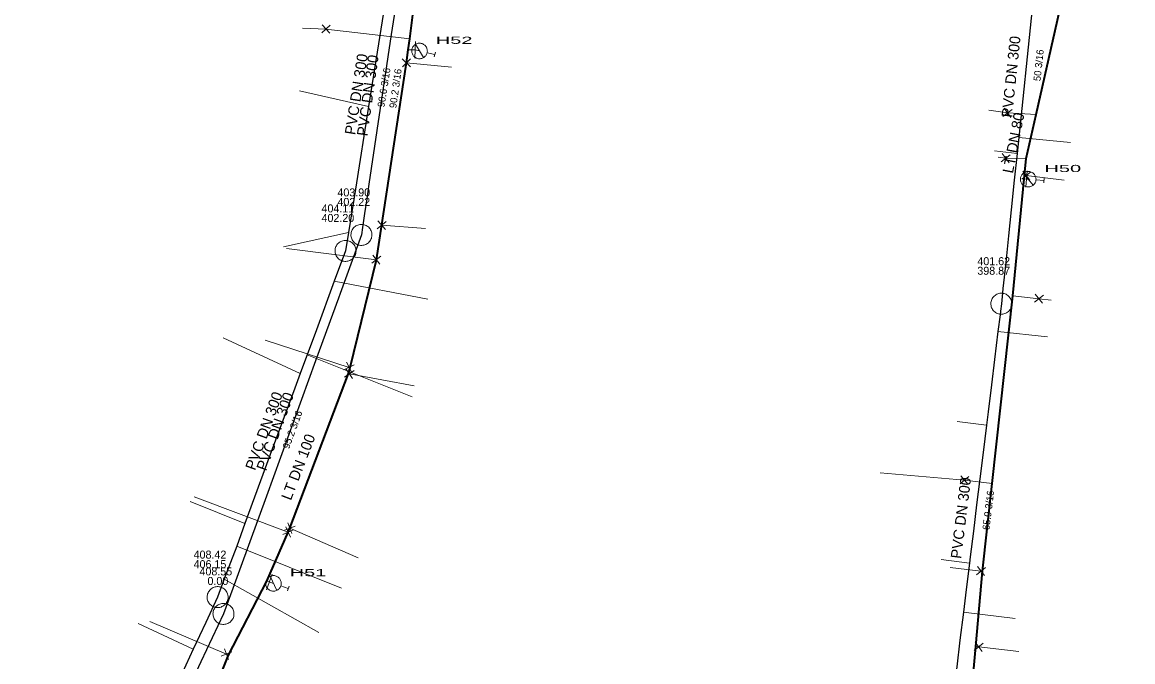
# Model space of a CAD drawing. Extents: x -772952 to -772403, y -1033777 to -1033210.
# Drawn here: x -772856.8 to -772731.9, y -1033502.9 to -1033431 of the extents above; entities that cross this region are included whole.
import ezdxf

# ---------------------------------------------------------------- set-up
doc = ezdxf.new("R2010")
doc.units = 0
doc.header["$LTSCALE"] = 0.36
for name, color, linetype, lineweight in [('15', 7, 'Continuous', 13), ('16', 7, 'Continuous', 35), ('2', 7, 'Continuous', 25), ('20', 7, 'Continuous', 13), ('4', 7, 'Continuous', 13), ('57', 7, 'Continuous', 13), ('59', 7, 'Continuous', 13)]:
    doc.layers.add(name, color=color, linetype=linetype, lineweight=lineweight)
for name, color, linetype in [('17', 7, 'Continuous'), ('3', 7, 'Continuous'), ('6', 7, 'Continuous')]:
    doc.layers.add(name, color=color, linetype=linetype)

msp = doc.modelspace()

# ---------------------------------------------------------------- linework, layer by layer
at = {"layer": '15'}
for p, q in [((-772822.125, -1033431.276), (-772823.076, -1033432.164)), ((-772822.161, -1033432.191), (-772823.039, -1033431.245)), ((-772812.608, -1033435), (-772812.532, -1033433.14)), ((-772813.093, -1033435.978), (-772814.014, -1033435.057)), ((-772814.009, -1033435.973), (-772813.093, -1033435.063)), ((-772745.439, -1033440.76), (-772746.482, -1033441.54)), ((-772745.574, -1033441.665), (-772746.345, -1033440.63)), ((-772745.654, -1033445.857), (-772746.694, -1033446.64)), ((-772745.786, -1033446.762), (-772746.56, -1033445.73)), ((-772744.369, -1033448.596), (-772743.344, -1033447.793)), ((-772744.254, -1033447.688), (-772743.46, -1033448.706)), ((-772743.919, -1033449.512), (-772743.748, -1033447.658)), ((-772816.822, -1033454.194), (-772815.835, -1033453.345)), ((-772816.749, -1033453.282), (-772815.909, -1033454.262)), ((-772816.409, -1033457.255), (-772817.436, -1033458.055)), ((-772816.527, -1033458.163), (-772817.317, -1033457.143)), ((-772742.841, -1033461.537), (-772742.038, -1033462.547)), ((-772742.947, -1033462.446), (-772741.93, -1033461.634)), ((-772819.416, -1033469.467), (-772820.575, -1033470.059)), ((-772820.496, -1033470.866), (-772819.424, -1033470.128)), ((-772820.326, -1033469.967), (-772819.597, -1033471.031)), ((-772819.702, -1033470.336), (-772820.287, -1033469.186)), ((-772750.302, -1033482.042), (-772751.299, -1033482.879)), ((-772750.386, -1033482.953), (-772751.214, -1033481.963)), ((-772827.265, -1033488.084), (-772826.054, -1033487.606)), ((-772826.591, -1033488.876), (-772827.121, -1033487.7)), ((-772826.897, -1033487.246), (-772826.425, -1033488.448)), ((-772826.265, -1033488.021), (-772827.451, -1033488.559)), ((-772748.437, -1033492.271), (-772749.458, -1033493.078)), ((-772748.548, -1033493.179), (-772749.346, -1033492.165)), ((-772829.278, -1033494.765), (-772828.655, -1033493.011)), ((-772833.537, -1033502.607), (-772834.016, -1033501.409)), ((-772749.709, -1033501.591), (-772748.686, -1033500.787)), ((-772749.596, -1033500.683), (-772748.801, -1033501.699)), ((-772833.174, -1033501.767), (-772834.382, -1033502.253))]:
    msp.add_line(p, q, dxfattribs=at)
at = {"layer": '16'}
for points in [[(-772752.004, -1033530.359), (-772751.19, -1033518.811), (-772750.826, -1033515.51), (-772749.541, -1033501.15), (-772748.782, -1033492.67), (-772747.697, -1033482.83), (-772745.37, -1033461.714), (-772744.103, -1033448.559), (-772744.068, -1033448.195), (-772743.857, -1033446.285), (-772742.735, -1033441.315), (-772739.627, -1033427.552), (-772737.918, -1033409.688), (-772737.464, -1033404.467), (-772736.037, -1033389.46), (-772734.688, -1033370.337), (-772732.3, -1033357.109), (-772731.88, -1033345.97)], [(-772837.765, -1033512.662), (-772833.548, -1033502.146), (-772829.238, -1033493.795), (-772826.857, -1033488.289), (-772826.66, -1033487.846), (-772820.068, -1033470.473), (-772819.886, -1033469.795), (-772816.921, -1033457.655), (-772813.552, -1033435.519), (-772813.35, -1033434.04), (-772813.183, -1033432.822), (-772812.813, -1033430.125), (-772811.638, -1033420.013), (-772811.429, -1033417.653), (-772810.102, -1033408.565), (-772809.872, -1033406.991), (-772809.089, -1033400.644), (-772808.375, -1033395.068), (-772807.557, -1033387.964), (-772806.853, -1033383.381), (-772806.021, -1033377.978)]]:
    msp.add_lwpolyline(points, dxfattribs=at)
at = {"layer": '2'}
for points in [[(-772741.06, -1033409.08), (-772741.253, -1033410.929), (-772741.326, -1033411.63), (-772741.587, -1033414.12), (-772741.871, -1033416.843), (-772742.189, -1033419.878), (-772742.495, -1033422.808), (-772742.806, -1033425.788), (-772743.066, -1033428.271), (-772743.3, -1033430.508), (-772744.701, -1033443.912), (-772744.889, -1033445.705), (-772745.203, -1033448.714), (-772745.553, -1033452.058), (-772745.859, -1033454.983), (-772746.171, -1033457.964), (-772746.344, -1033459.622), (-772746.477, -1033460.894), (-772746.527, -1033461.369), (-772746.66, -1033462.606)], [(-772814.42, -1033419.15), (-772814.998, -1033422.779), (-772815.417, -1033425.405), (-772816.014, -1033429.153), (-772817.813, -1033440.441), (-772819.293, -1033449.728), (-772820.068, -1033454.588), (-772820.4, -1033456.67)], [(-772813.59, -1033421.19), (-772813.756, -1033422.304), (-772813.954, -1033423.632), (-772814.184, -1033425.18), (-772814.339, -1033425.976), (-772814.533, -1033427.52), (-772815.252, -1033432.346), (-772815.998, -1033437.348), (-772816.86, -1033443.13), (-772817.761, -1033449.175), (-772818.006, -1033450.823), (-772818.251, -1033452.464), (-772818.488, -1033454.051), (-772818.61, -1033454.87)], [(-772818.61, -1033454.87), (-772821.012, -1033461.472), (-772821.192, -1033461.989), (-772821.867, -1033463.82), (-772823.76, -1033469.022), (-772829.295, -1033484.231), (-772832.183, -1033492.167), (-772833.081, -1033494.635), (-772834.12, -1033497.49)], [(-772820.4, -1033456.67), (-772821.658, -1033460.076), (-772823.677, -1033465.542), (-772825.485, -1033470.437), (-772826.102, -1033472.107), (-772828.853, -1033479.555), (-772831.719, -1033487.314), (-772832.635, -1033489.888), (-772833.341, -1033491.706), (-772834.069, -1033493.675), (-772834.78, -1033495.6)], [(-772746.66, -1033462.606), (-772746.76, -1033463.455), (-772746.808, -1033463.844), (-772747.038, -1033465.715), (-772747.425, -1033468.865), (-772747.777, -1033471.721), (-772748.153, -1033474.782), (-772748.335, -1033476.264), (-772748.712, -1033479.323), (-772749.08, -1033482.314), (-772749.439, -1033485.239), (-772749.803, -1033488.195), (-772750.155, -1033491.056), (-772750.242, -1033491.766), (-772750.606, -1033494.725), (-772750.924, -1033497.308), (-772751.311, -1033500.451), (-772751.677, -1033503.432), (-772752.043, -1033506.407), (-772752.158, -1033507.342), (-772752.198, -1033507.662), (-772752.29, -1033508.384)], [(-772834.78, -1033495.6), (-772836.114, -1033498.463), (-772837.51, -1033501.461), (-772838.768, -1033504.161), (-772840.12, -1033507.062), (-772842.931, -1033513.095), (-772845.54, -1033518.695), (-772849.358, -1033526.891), (-772852.073, -1033532.717), (-772853.674, -1033536.155), (-772854.426, -1033537.769), (-772855.508, -1033540.092), (-772855.782, -1033540.679), (-772856.3, -1033541.79)], [(-772834.12, -1033497.489), (-772836.663, -1033502.872), (-772837.696, -1033505.057), (-772838.705, -1033507.192), (-772840.489, -1033510.965), (-772843.322, -1033516.96), (-772845.177, -1033520.885), (-772847.84, -1033526.52), (-772850.14, -1033531.386), (-772853.138, -1033537.728), (-772854.606, -1033540.835), (-772856.75, -1033545.37)]]:
    msp.add_lwpolyline(points, dxfattribs=at)
at = {"layer": '20'}
for p, q in [((-772811.613, -1033434.926), (-772812.535, -1033433.438)), ((-772811.211, -1033434.384), (-772810.351, -1033434.587)), ((-772810.289, -1033434.324), (-772810.413, -1033434.851)), ((-772743.075, -1033449.271), (-772744.194, -1033447.925)), ((-772742.752, -1033448.679), (-772741.872, -1033448.76)), ((-772741.847, -1033448.491), (-772741.897, -1033449.03)), ((-772828.124, -1033494.838), (-772828.877, -1033493.258)), ((-772827.665, -1033494.344), (-772826.832, -1033494.64)), ((-772826.742, -1033494.385), (-772826.922, -1033494.895))]:
    msp.add_line(p, q, dxfattribs=at)
for points in [[(-772812.274, -1033435.038), (-772812.186, -1033435.055), (-772812.095, -1033435.062), (-772812.002, -1033435.059), (-772811.913, -1033435.047), (-772811.823, -1033435.025), (-772811.736, -1033434.995), (-772811.654, -1033434.954), (-772811.576, -1033434.907), (-772811.505, -1033434.85), (-772811.438, -1033434.787), (-772811.379, -1033434.717), (-772811.326, -1033434.641), (-772811.282, -1033434.561), (-772811.248, -1033434.476), (-772811.223, -1033434.388), (-772811.206, -1033434.297), (-772811.199, -1033434.207), (-772811.202, -1033434.115), (-772811.216, -1033434.024), (-772811.238, -1033433.934), (-772811.269, -1033433.849), (-772811.307, -1033433.766), (-772811.357, -1033433.689), (-772811.412, -1033433.616), (-772811.476, -1033433.55), (-772811.546, -1033433.49), (-772811.621, -1033433.44), (-772811.703, -1033433.396), (-772811.787, -1033433.361), (-772811.875, -1033433.334), (-772811.964, -1033433.32), (-772812.055, -1033433.313), (-772812.148, -1033433.315), (-772812.237, -1033433.327), (-772812.327, -1033433.349), (-772812.414, -1033433.38), (-772812.496, -1033433.421), (-772812.574, -1033433.468), (-772812.645, -1033433.525), (-772812.712, -1033433.588), (-772812.771, -1033433.658), (-772812.824, -1033433.734), (-772812.866, -1033433.814), (-772812.902, -1033433.898), (-772812.927, -1033433.987), (-772812.944, -1033434.077), (-772812.949, -1033434.169), (-772812.948, -1033434.259), (-772812.934, -1033434.351), (-772812.912, -1033434.44), (-772812.881, -1033434.526), (-772812.843, -1033434.609), (-772812.793, -1033434.686), (-772812.738, -1033434.759), (-772812.674, -1033434.825), (-772812.604, -1033434.885), (-772812.529, -1033434.935), (-772812.447, -1033434.979), (-772812.363, -1033435.013), (-772812.276, -1033435.038)], [(-772743.714, -1033449.474), (-772743.624, -1033449.478), (-772743.533, -1033449.472), (-772743.442, -1033449.457), (-772743.355, -1033449.433), (-772743.27, -1033449.398), (-772743.187, -1033449.356), (-772743.112, -1033449.304), (-772743.041, -1033449.247), (-772742.978, -1033449.18), (-772742.921, -1033449.109), (-772742.872, -1033449.031), (-772742.83, -1033448.949), (-772742.798, -1033448.863), (-772742.776, -1033448.775), (-772742.764, -1033448.684), (-772742.759, -1033448.592), (-772742.765, -1033448.501), (-772742.781, -1033448.411), (-772742.807, -1033448.322), (-772742.841, -1033448.237), (-772742.884, -1033448.157), (-772742.933, -1033448.08), (-772742.993, -1033448.01), (-772743.057, -1033447.946), (-772743.13, -1033447.889), (-772743.208, -1033447.839), (-772743.289, -1033447.8), (-772743.376, -1033447.768), (-772743.464, -1033447.745), (-772743.555, -1033447.731), (-772743.646, -1033447.729), (-772743.737, -1033447.734), (-772743.828, -1033447.75), (-772743.915, -1033447.774), (-772744, -1033447.809), (-772744.083, -1033447.851), (-772744.158, -1033447.902), (-772744.229, -1033447.96), (-772744.292, -1033448.027), (-772744.349, -1033448.098), (-772744.398, -1033448.176), (-772744.44, -1033448.258), (-772744.47, -1033448.344), (-772744.494, -1033448.432), (-772744.506, -1033448.523), (-772744.511, -1033448.615), (-772744.503, -1033448.706), (-772744.489, -1033448.796), (-772744.463, -1033448.885), (-772744.429, -1033448.97), (-772744.386, -1033449.05), (-772744.337, -1033449.127), (-772744.277, -1033449.197), (-772744.213, -1033449.261), (-772744.14, -1033449.318), (-772744.062, -1033449.367), (-772743.981, -1033449.407), (-772743.894, -1033449.439), (-772743.806, -1033449.461), (-772743.716, -1033449.474)], [(-772828.793, -1033494.877), (-772828.707, -1033494.904), (-772828.618, -1033494.921), (-772828.525, -1033494.928), (-772828.435, -1033494.926), (-772828.344, -1033494.914), (-772828.253, -1033494.893), (-772828.168, -1033494.862), (-772828.084, -1033494.823), (-772828.008, -1033494.774), (-772827.935, -1033494.719), (-772827.868, -1033494.656), (-772827.807, -1033494.586), (-772827.755, -1033494.511), (-772827.712, -1033494.431), (-772827.677, -1033494.346), (-772827.65, -1033494.258), (-772827.633, -1033494.168), (-772827.627, -1033494.077), (-772827.63, -1033493.985), (-772827.642, -1033493.894), (-772827.664, -1033493.805), (-772827.692, -1033493.719), (-772827.733, -1033493.636), (-772827.78, -1033493.558), (-772827.837, -1033493.485), (-772827.9, -1033493.418), (-772827.968, -1033493.36), (-772828.045, -1033493.307), (-772828.125, -1033493.264), (-772828.21, -1033493.227), (-772828.297, -1033493.203), (-772828.386, -1033493.186), (-772828.479, -1033493.179), (-772828.569, -1033493.181), (-772828.66, -1033493.193), (-772828.751, -1033493.214), (-772828.836, -1033493.245), (-772828.92, -1033493.283), (-772828.996, -1033493.332), (-772829.069, -1033493.387), (-772829.136, -1033493.451), (-772829.197, -1033493.52), (-772829.247, -1033493.596), (-772829.292, -1033493.675), (-772829.327, -1033493.761), (-772829.354, -1033493.849), (-772829.369, -1033493.939), (-772829.377, -1033494.029), (-772829.374, -1033494.122), (-772829.362, -1033494.213), (-772829.34, -1033494.301), (-772829.311, -1033494.388), (-772829.271, -1033494.47), (-772829.224, -1033494.548), (-772829.167, -1033494.622), (-772829.104, -1033494.689), (-772829.036, -1033494.747), (-772828.959, -1033494.8), (-772828.879, -1033494.843), (-772828.795, -1033494.877)]]:
    msp.add_lwpolyline(points, dxfattribs=at)
at = {"layer": '4'}
for points in [[(-772817.429, -1033454.87), (-772817.435, -1033454.751), (-772817.453, -1033454.634), (-772817.482, -1033454.518), (-772817.523, -1033454.407), (-772817.575, -1033454.3), (-772817.638, -1033454.199), (-772817.711, -1033454.104), (-772817.792, -1033454.018), (-772817.882, -1033453.94), (-772817.98, -1033453.871), (-772818.083, -1033453.813), (-772818.192, -1033453.766), (-772818.306, -1033453.729), (-772818.422, -1033453.704), (-772818.54, -1033453.692), (-772818.659, -1033453.691), (-772818.778, -1033453.702), (-772818.894, -1033453.725), (-772819.008, -1033453.759), (-772819.118, -1033453.805), (-772819.223, -1033453.862), (-772819.321, -1033453.929), (-772819.412, -1033454.005), (-772819.495, -1033454.09), (-772819.569, -1033454.184), (-772819.633, -1033454.284), (-772819.687, -1033454.39), (-772819.73, -1033454.501), (-772819.762, -1033454.615), (-772819.781, -1033454.733), (-772819.789, -1033454.852), (-772819.785, -1033454.97), (-772819.769, -1033455.088), (-772819.741, -1033455.204), (-772819.702, -1033455.316), (-772819.651, -1033455.424), (-772819.59, -1033455.526), (-772819.519, -1033455.622), (-772819.439, -1033455.709), (-772819.35, -1033455.789), (-772819.254, -1033455.859), (-772819.151, -1033455.919), (-772819.043, -1033455.968), (-772818.93, -1033456.006), (-772818.814, -1033456.032), (-772818.696, -1033456.047), (-772818.577, -1033456.05), (-772818.459, -1033456.041), (-772818.341, -1033456.02), (-772818.227, -1033455.987), (-772818.117, -1033455.943), (-772818.011, -1033455.888), (-772817.912, -1033455.822), (-772817.819, -1033455.747), (-772817.735, -1033455.663), (-772817.66, -1033455.571), (-772817.594, -1033455.472), (-772817.538, -1033455.367), (-772817.494, -1033455.257), (-772817.46, -1033455.143), (-772817.439, -1033455.026), (-772817.429, -1033454.907)], [(-772819.218, -1033456.67), (-772819.225, -1033456.551), (-772819.243, -1033456.434), (-772819.272, -1033456.318), (-772819.313, -1033456.207), (-772819.365, -1033456.1), (-772819.428, -1033455.999), (-772819.5, -1033455.904), (-772819.581, -1033455.818), (-772819.672, -1033455.74), (-772819.77, -1033455.671), (-772819.873, -1033455.613), (-772819.982, -1033455.566), (-772820.096, -1033455.529), (-772820.212, -1033455.504), (-772820.33, -1033455.492), (-772820.449, -1033455.491), (-772820.568, -1033455.502), (-772820.684, -1033455.525), (-772820.798, -1033455.559), (-772820.907, -1033455.605), (-772821.012, -1033455.662), (-772821.111, -1033455.729), (-772821.201, -1033455.805), (-772821.285, -1033455.89), (-772821.358, -1033455.984), (-772821.423, -1033456.084), (-772821.477, -1033456.19), (-772821.52, -1033456.301), (-772821.552, -1033456.415), (-772821.571, -1033456.533), (-772821.579, -1033456.652), (-772821.575, -1033456.77), (-772821.559, -1033456.888), (-772821.531, -1033457.004), (-772821.492, -1033457.116), (-772821.441, -1033457.224), (-772821.38, -1033457.326), (-772821.309, -1033457.422), (-772821.228, -1033457.509), (-772821.14, -1033457.589), (-772821.044, -1033457.659), (-772820.941, -1033457.719), (-772820.833, -1033457.768), (-772820.72, -1033457.806), (-772820.603, -1033457.832), (-772820.486, -1033457.847), (-772820.367, -1033457.85), (-772820.249, -1033457.841), (-772820.13, -1033457.82), (-772820.017, -1033457.787), (-772819.907, -1033457.743), (-772819.801, -1033457.688), (-772819.701, -1033457.622), (-772819.608, -1033457.547), (-772819.525, -1033457.463), (-772819.45, -1033457.371), (-772819.384, -1033457.272), (-772819.328, -1033457.167), (-772819.284, -1033457.057), (-772819.25, -1033456.943), (-772819.228, -1033456.826), (-772819.218, -1033456.707)], [(-772745.48, -1033462.606), (-772745.486, -1033462.487), (-772745.504, -1033462.37), (-772745.533, -1033462.254), (-772745.574, -1033462.143), (-772745.626, -1033462.036), (-772745.689, -1033461.935), (-772745.762, -1033461.84), (-772745.843, -1033461.754), (-772745.933, -1033461.676), (-772746.031, -1033461.607), (-772746.134, -1033461.549), (-772746.243, -1033461.502), (-772746.357, -1033461.465), (-772746.473, -1033461.44), (-772746.591, -1033461.428), (-772746.71, -1033461.427), (-772746.829, -1033461.438), (-772746.945, -1033461.461), (-772747.059, -1033461.495), (-772747.169, -1033461.541), (-772747.274, -1033461.598), (-772747.372, -1033461.665), (-772747.463, -1033461.741), (-772747.546, -1033461.826), (-772747.62, -1033461.92), (-772747.684, -1033462.02), (-772747.738, -1033462.126), (-772747.781, -1033462.237), (-772747.813, -1033462.351), (-772747.832, -1033462.469), (-772747.84, -1033462.588), (-772747.836, -1033462.706), (-772747.82, -1033462.824), (-772747.792, -1033462.94), (-772747.753, -1033463.052), (-772747.702, -1033463.16), (-772747.641, -1033463.262), (-772747.57, -1033463.358), (-772747.49, -1033463.445), (-772747.401, -1033463.525), (-772747.305, -1033463.595), (-772747.202, -1033463.655), (-772747.094, -1033463.704), (-772746.981, -1033463.742), (-772746.865, -1033463.768), (-772746.747, -1033463.783), (-772746.628, -1033463.786), (-772746.51, -1033463.777), (-772746.392, -1033463.756), (-772746.278, -1033463.723), (-772746.168, -1033463.679), (-772746.062, -1033463.624), (-772745.963, -1033463.558), (-772745.87, -1033463.483), (-772745.786, -1033463.399), (-772745.711, -1033463.307), (-772745.645, -1033463.208), (-772745.589, -1033463.103), (-772745.545, -1033462.993), (-772745.511, -1033462.879), (-772745.49, -1033462.762), (-772745.48, -1033462.643)], [(-772833.6, -1033495.6), (-772833.606, -1033495.481), (-772833.624, -1033495.364), (-772833.653, -1033495.248), (-772833.694, -1033495.137), (-772833.746, -1033495.03), (-772833.809, -1033494.929), (-772833.882, -1033494.834), (-772833.963, -1033494.748), (-772834.053, -1033494.67), (-772834.151, -1033494.601), (-772834.254, -1033494.543), (-772834.363, -1033494.496), (-772834.477, -1033494.459), (-772834.593, -1033494.434), (-772834.711, -1033494.422), (-772834.83, -1033494.421), (-772834.949, -1033494.432), (-772835.065, -1033494.455), (-772835.179, -1033494.489), (-772835.289, -1033494.535), (-772835.394, -1033494.592), (-772835.492, -1033494.659), (-772835.583, -1033494.735), (-772835.666, -1033494.82), (-772835.74, -1033494.914), (-772835.804, -1033495.014), (-772835.858, -1033495.12), (-772835.901, -1033495.231), (-772835.933, -1033495.345), (-772835.952, -1033495.463), (-772835.96, -1033495.582), (-772835.956, -1033495.7), (-772835.94, -1033495.818), (-772835.912, -1033495.934), (-772835.873, -1033496.046), (-772835.822, -1033496.154), (-772835.761, -1033496.256), (-772835.69, -1033496.352), (-772835.61, -1033496.439), (-772835.521, -1033496.519), (-772835.425, -1033496.589), (-772835.322, -1033496.649), (-772835.214, -1033496.698), (-772835.101, -1033496.736), (-772834.985, -1033496.762), (-772834.867, -1033496.777), (-772834.748, -1033496.78), (-772834.63, -1033496.771), (-772834.512, -1033496.75), (-772834.398, -1033496.717), (-772834.288, -1033496.673), (-772834.182, -1033496.618), (-772834.083, -1033496.552), (-772833.99, -1033496.477), (-772833.906, -1033496.393), (-772833.831, -1033496.301), (-772833.765, -1033496.202), (-772833.709, -1033496.097), (-772833.665, -1033495.987), (-772833.631, -1033495.873), (-772833.61, -1033495.756), (-772833.6, -1033495.637)], [(-772832.94, -1033497.489), (-772832.946, -1033497.37), (-772832.964, -1033497.253), (-772832.993, -1033497.137), (-772833.034, -1033497.026), (-772833.086, -1033496.919), (-772833.149, -1033496.818), (-772833.222, -1033496.723), (-772833.303, -1033496.637), (-772833.393, -1033496.559), (-772833.491, -1033496.49), (-772833.594, -1033496.432), (-772833.703, -1033496.385), (-772833.817, -1033496.348), (-772833.933, -1033496.323), (-772834.051, -1033496.311), (-772834.17, -1033496.31), (-772834.289, -1033496.321), (-772834.405, -1033496.344), (-772834.519, -1033496.378), (-772834.629, -1033496.424), (-772834.733, -1033496.481), (-772834.832, -1033496.548), (-772834.923, -1033496.624), (-772835.006, -1033496.709), (-772835.08, -1033496.803), (-772835.144, -1033496.903), (-772835.198, -1033497.009), (-772835.241, -1033497.12), (-772835.273, -1033497.234), (-772835.292, -1033497.352), (-772835.3, -1033497.471), (-772835.296, -1033497.589), (-772835.28, -1033497.707), (-772835.252, -1033497.823), (-772835.213, -1033497.935), (-772835.162, -1033498.043), (-772835.101, -1033498.145), (-772835.03, -1033498.241), (-772834.95, -1033498.328), (-772834.861, -1033498.408), (-772834.765, -1033498.478), (-772834.662, -1033498.538), (-772834.554, -1033498.587), (-772834.441, -1033498.625), (-772834.325, -1033498.651), (-772834.207, -1033498.666), (-772834.088, -1033498.669), (-772833.97, -1033498.66), (-772833.852, -1033498.639), (-772833.738, -1033498.606), (-772833.628, -1033498.562), (-772833.522, -1033498.507), (-772833.423, -1033498.441), (-772833.33, -1033498.366), (-772833.246, -1033498.282), (-772833.171, -1033498.19), (-772833.105, -1033498.091), (-772833.049, -1033497.986), (-772833.005, -1033497.876), (-772832.971, -1033497.762), (-772832.95, -1033497.645), (-772832.94, -1033497.526)]]:
    msp.add_lwpolyline(points, close=True, dxfattribs=at)
at = {"layer": '57'}
for p, q in [((-772817.813, -1033440.441), (-772825.57, -1033438.67)), ((-772744.701, -1033443.912), (-772738.87, -1033444.48)), ((-772744.889, -1033445.705), (-772747.44, -1033445.43)), ((-772820.068, -1033454.588), (-772827.36, -1033456.2)), ((-772821.658, -1033460.076), (-772811.14, -1033462.09)), ((-772825.485, -1033470.437), (-772834.14, -1033466.44)), ((-772747.038, -1033465.715), (-772741.47, -1033466.34)), ((-772824.719, -1033468.363), (-772812.92, -1033473.09)), ((-772748.335, -1033476.264), (-772751.64, -1033475.86)), ((-772831.719, -1033487.314), (-772837.85, -1033484.86)), ((-772832.635, -1033489.888), (-772820.85, -1033494.58)), ((-772750.242, -1033491.766), (-772753.42, -1033491.36)), ((-772834.041, -1033493.599), (-772823.411, -1033499.572)), ((-772750.924, -1033497.308), (-772745.1, -1033498.02)), ((-772837.51, -1033501.461), (-772843.73, -1033498.55))]:
    msp.add_line(p, q, dxfattribs=at)
at = {"layer": '59'}
for p, q in [((-772816.33, -1033453.771), (-772811.418, -1033454.136)), ((-772816.922, -1033457.655), (-772827.035, -1033456.401)), ((-772826.857, -1033488.29), (-772837.434, -1033484.316)), ((-772826.661, -1033487.846), (-772818.985, -1033491.168))]:
    msp.add_line(p, q, dxfattribs=at)
for points in [[(-772813.183, -1033432.822), (-772822.6, -1033431.72), (-772825.23, -1033431.63)], [(-772813.35, -1033434.04), (-772812.571, -1033434.071), (-772812.075, -1033434.188)], [(-772813.553, -1033435.519), (-772813.553, -1033435.519), (-772808.484, -1033436.007)], [(-772742.735, -1033441.315), (-772745.96, -1033441.15), (-772748.05, -1033440.85)], [(-772743.857, -1033446.28), (-772746.173, -1033446.248), (-772747.008, -1033446.131)], [(-772744.103, -1033448.56), (-772743.834, -1033448.586), (-772743.635, -1033448.604)], [(-772744.068, -1033448.196), (-772743.858, -1033448.196), (-772739.601, -1033448.709)], [(-772745.371, -1033461.715), (-772742.44, -1033462.041), (-772741.051, -1033462.197)], [(-772819.886, -1033469.795), (-772819.995, -1033469.763), (-772829.434, -1033466.713)], [(-772820.068, -1033470.474), (-772819.962, -1033470.498), (-772812.685, -1033471.836)], [(-772747.697, -1033482.83), (-772750.8, -1033482.46), (-772760.29, -1033481.64)], [(-772748.782, -1033492.67), (-772748.947, -1033492.674), (-772752.41, -1033492.271)], [(-772829.238, -1033493.795), (-772828.967, -1033493.889), (-772828.502, -1033494.054)], [(-772833.549, -1033502.147), (-772833.777, -1033502.01), (-772842.391, -1033498.346)], [(-772749.541, -1033501.15), (-772749.2, -1033501.19), (-772744.68, -1033501.73)]]:
    msp.add_lwpolyline(points, dxfattribs=at)

# ---------------------------------------------------------------- texts
at = {"layer": '17'}
for s, rotation, p in [('LT DN 80', 79, (-772745.363, -1033448.011)), ('LT DN 100 ', 69, (-772826.543, -1033484.801))]:
    msp.add_text(s, height=1.2, rotation=rotation, dxfattribs=at).set_placement(p)
at = {"layer": '20', "width": 2.1}
for s, p in [('H52 ', (-772810.248, -1033433.384)), ('H50 ', (-772741.809, -1033447.799)), ('H51 ', (-772826.676, -1033493.248))]:
    msp.add_text(s, height=0.8, dxfattribs=at).set_placement(p)
at = {"layer": '3'}
for s, height, rotation, p in [('PVC DN 300', 1.2, 84, (-772745.451, -1033441.708)), ('50 3/16', 0.8, 84, (-772742.259, -1033437.616)), ('PVC DN 300', 1.2, 81, (-772819.314, -1033443.681)), ('PVC DN 300', 1.2, 82, (-772817.944, -1033443.819)), ('90.6 3/16', 0.8, 81, (-772816.032, -1033440.559)), ('90.2 3/16', 0.8, 82, (-772814.695, -1033440.664)), ('PVC DN 300', 1.2, 70, (-772830.58, -1033481.425)), ('PVC DN 300', 1.2, 70, (-772829.328, -1033481.485)), ('95.2 3/16', 0.8, 70, (-772826.754, -1033479.001)), ('PVC DN 300', 1.2, 83, (-772751.173, -1033491.331)), ('65.9 3/16', 0.8, 83, (-772748.004, -1033488.094))]:
    msp.add_text(s, height=height, rotation=rotation, dxfattribs=at).set_placement(p)
at = {"layer": '6'}
for s, p in [('403.90', (-772821.309, -1033450.539)), ('404.11', (-772823.098, -1033452.338)), ('402.22', (-772821.309, -1033451.616)), ('402.20', (-772823.098, -1033453.415)), ('401.62', (-772749.358, -1033458.274)), ('398.87', (-772749.358, -1033459.351)), ('408.42', (-772837.478, -1033491.268)), ('406.15', (-772837.478, -1033492.345)), ('408.55', (-772836.819, -1033493.158)), ('0.00', (-772835.919, -1033494.235))]:
    msp.add_text(s, height=0.9, dxfattribs=at).set_placement(p)

doc.saveas('drawing.dxf')
